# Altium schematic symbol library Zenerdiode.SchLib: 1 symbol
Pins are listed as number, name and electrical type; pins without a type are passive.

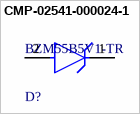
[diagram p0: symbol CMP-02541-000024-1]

## CMP-02541-000024-1
designator D?, comment BZM55B5V1-TR
DIODE ZENER 5.1V 500MW MICROMELF; Test Current: 5mA; Element Configuration: Single; Impedance: 60R; ESD Protection: No; Voltage Tolerance: 2%; Max Reverse Leakage Current: 100nA
footprint FP-6_560-5007_01-4-MFG
pins: 1 C, 2 A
